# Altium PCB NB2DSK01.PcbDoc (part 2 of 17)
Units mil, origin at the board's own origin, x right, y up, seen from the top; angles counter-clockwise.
Board outline 11815 x 6500.03 mil, 8 copper layers (Top Layer, MidLayer1, MidLayer2, GND, PWR, MidLayer3, MidLayer4, Bottom Layer), stack 74.62 mil thick; 798 components, 1002 nets, 3927 pads, 3182 vias.
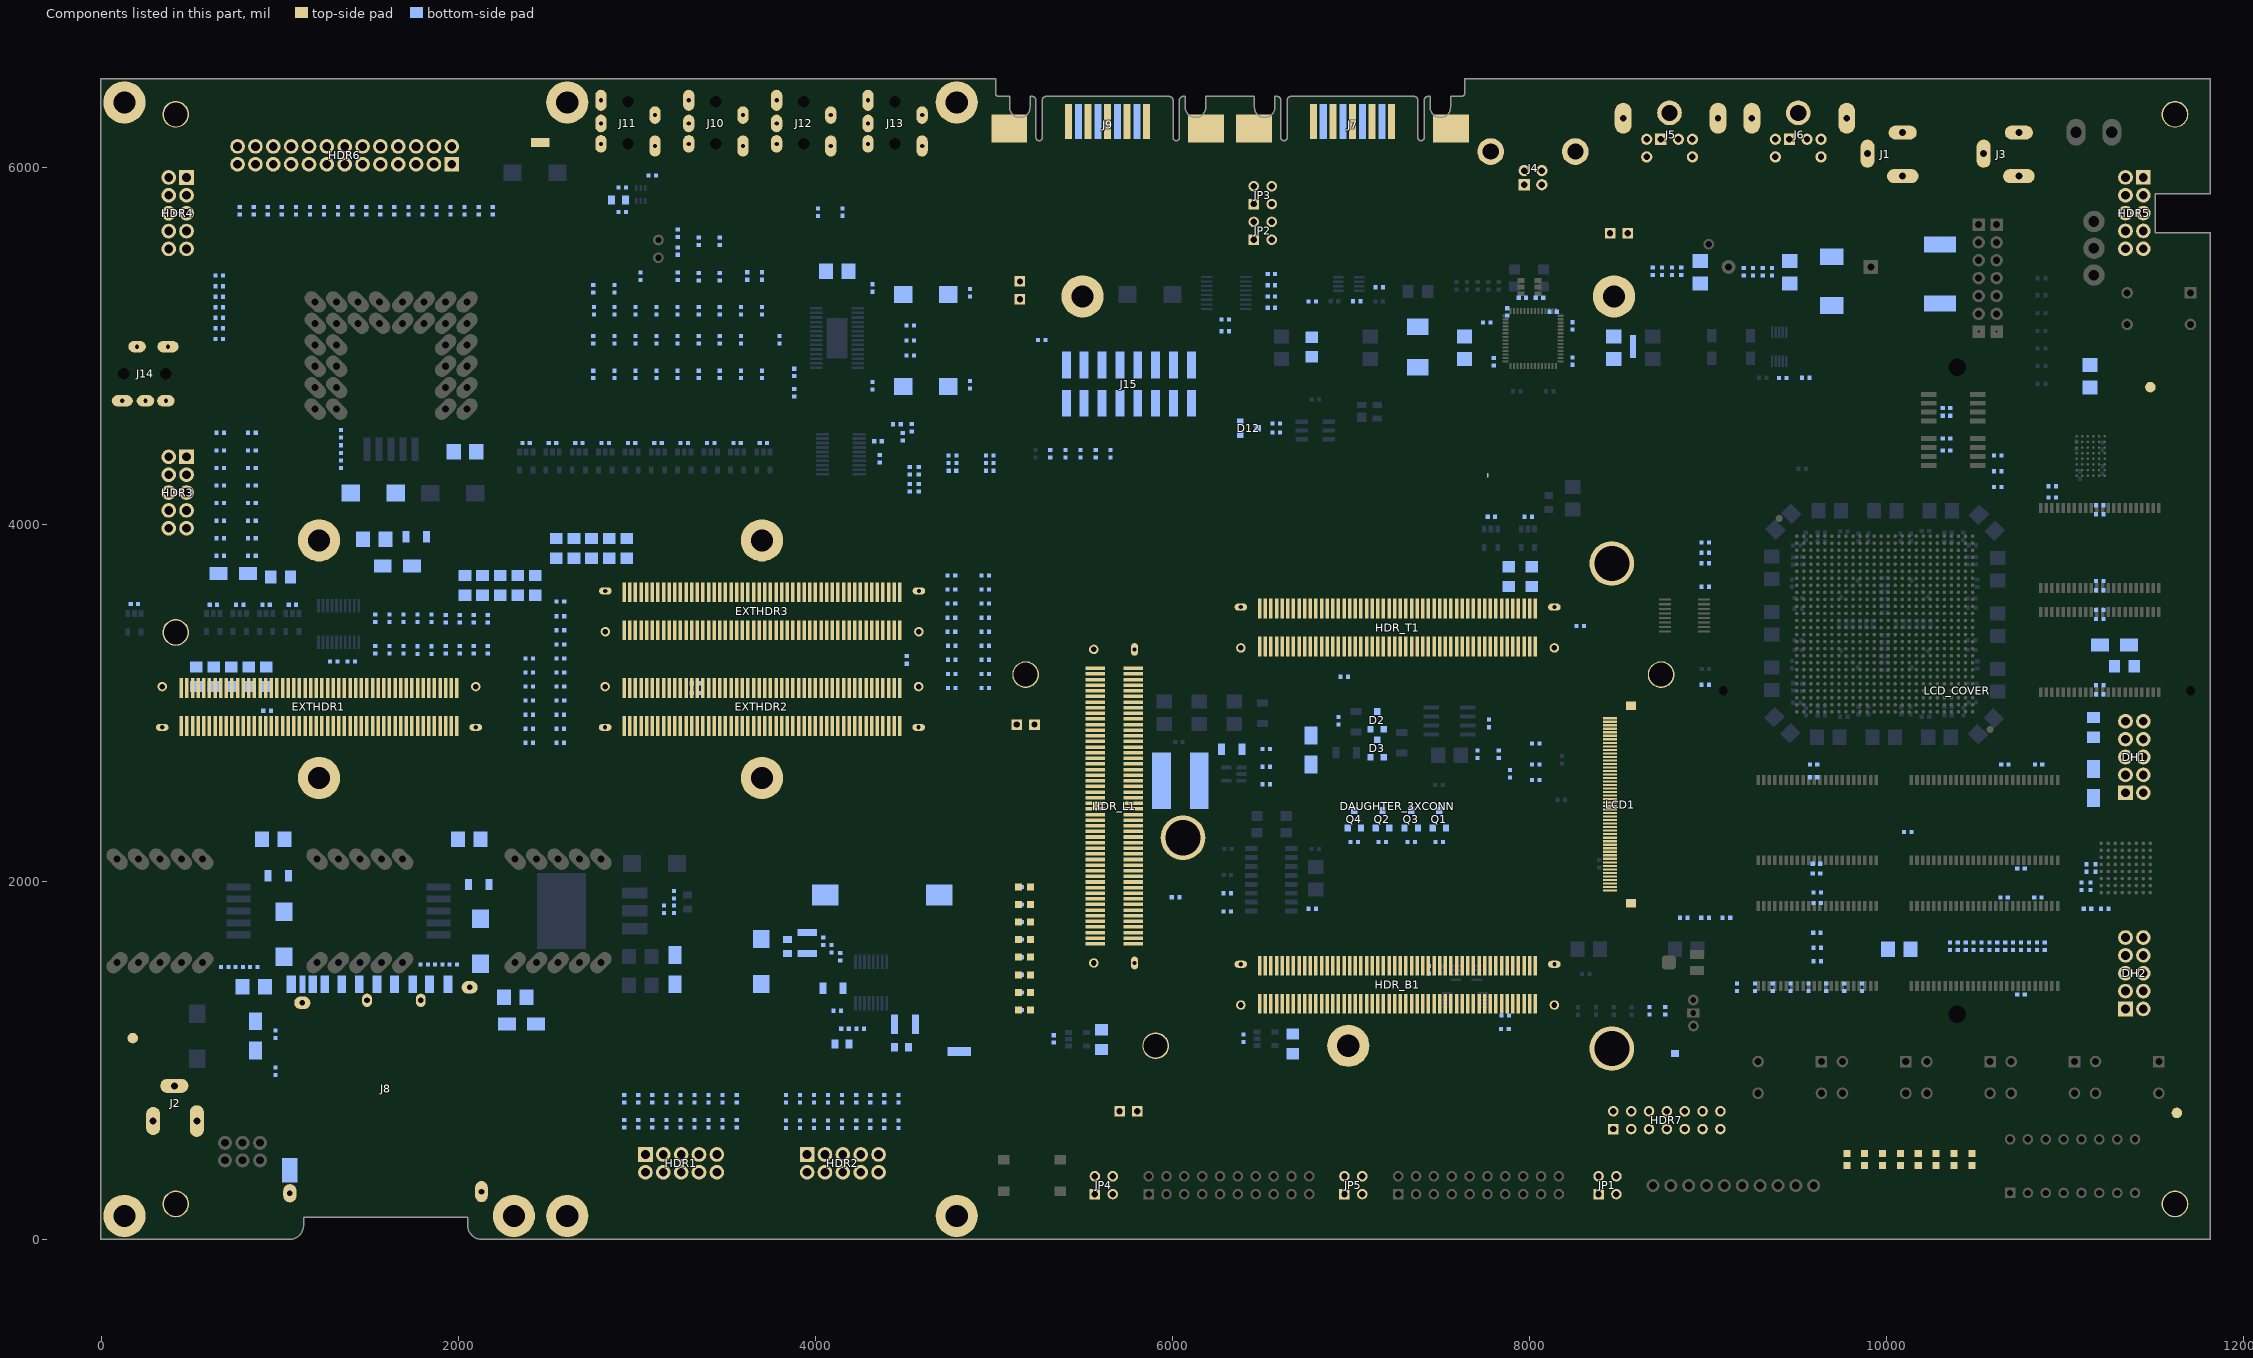
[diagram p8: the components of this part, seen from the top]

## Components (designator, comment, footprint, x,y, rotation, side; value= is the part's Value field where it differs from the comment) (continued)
C144 "1uF 25V" CAPC3216-STAR 6330.71,2744.1 r0 bottom locked (schematic designator C6)
C145 "470pF 50V" CAPC1005-STAR 4165.68,1178.45 r180 bottom (schematic designator C1)
C146 "10uF 10V" CAPC2012-STAR 4482.68,1074.45 r180 bottom (schematic designator C2)
C147 "22uF 10V" CAPC3225-STAR 4500.68,1203.45 r180 bottom (schematic designator C3)
C148 "10uF 10V" CAPC2012-STAR 3843.68,1638.45 r90 bottom (schematic designator C4)
C149 "22uF 10V" CAPC3225-STAR 3953.68,1658.45 r90 bottom (schematic designator C5)
C150 "220uF 10V" CAPC7343-STAR 3696.85,1555.12 r270 bottom (schematic designator C6)
C151 "1uF 25V" CAPC3216-STAR 4098.68,1405.45 r180 bottom (schematic designator C7)
C152 "10uF 10V" CAPC2012-STAR 4149.68,1093.45 r0 bottom (schematic designator C8)
C153 "0.1uF 16V" CAPC1005-STAR 6553.81,5405.51 r0 bottom (schematic designator C1)
C154 "0.1uF 16V" CAPC1005-STAR 6553.81,5342.52 r180 bottom (schematic designator C3)
C155 "0.1uF 16V" CAPC1005-STAR 6553.81,5279.53 r0 bottom (schematic designator C2)
C156 "0.1uF 16V" CAPC1005-STAR 6553.81,5216.54 r0 bottom (schematic designator C4)
C157 "1uF 25V" CAPC3216-STAR 2114.17,1986.59 r0 bottom (schematic designator C2)
C158 "10uF 20V" CAPC3528-STAR 2061.02,2238.45 r180 bottom (schematic designator C1)
C159 "10uF 20V" CAPC3528-STAR 2318.68,1353.45 r0 bottom (schematic designator C3)
C160 "220uF 10V" CAPC7343-STAR 2123.68,1668.45 r90 bottom (schematic designator C4)
C161 "1uF 25V" CAPC3216-STAR 992.13,2034.68 r0 bottom (schematic designator C2)
C162 "10uF 20V" CAPC3528-STAR 963.68,2238.45 r180 bottom (schematic designator C1)
C163 "10uF 20V" CAPC3528-STAR 853.68,1413.45 r180 bottom (schematic designator C3)
C164 "220uF 10V" CAPC7343-STAR 1023.68,1707.45 r90 bottom (schematic designator C4)
C165 "1uF 25V" CAPC3216-STAR 1763.68,3933.45 r180 bottom (schematic designator C2)
C166 "10uF 20V" CAPC3528-STAR 2037.4,4409.45 r0 bottom (schematic designator C1)
C167 "10uF 20V" CAPC3528-STAR 1528.68,3918.45 r0 bottom (schematic designator C3)
C168 "220uF 10V" CAPC7343-STAR 1523.68,4178.45 r0 bottom (schematic designator C4)
C169 "10uF 20V" CAPC3528-STAR 8955.24,5414.21 r270 bottom (schematic designator C1)
C170 "10uF 20V" CAPC3528-STAR 9456.18,5414.21 r270 bottom (schematic designator C1)
C171 "1uF 6.3v" CAPC1005-STAR 2874.02,4842.52 r270 bottom locked (schematic designator C6)
C172 "4.7nF 25V" CAPC1005-STAR 2755.91,4842.52 r270 bottom locked (schematic designator C7)
C173 "1uF 6.3v" CAPC1005-STAR 2992.13,4842.52 r270 bottom locked (schematic designator C8)
C174 "0.1uF 16V" CAPC1005-STAR 3881.89,4740.16 r270 bottom locked (schematic designator C15)
C175 "1uF 6.3v" CAPC1005-STAR 3346.46,4842.52 r270 bottom locked (schematic designator C9)
C176 "1uF 6.3v" CAPC1005-STAR 3582.68,4842.52 r270 bottom locked (schematic designator C11)
C177 "220uF 10V" CAPC7343-STAR 4618.11,5290.66 r0 bottom locked (schematic designator C12)
C178 "1uF 6.3v" CAPC1005-STAR 2755.91,5322.84 r90 bottom locked (schematic designator C26)
C179 "1uF 6.3v" CAPC1005-STAR 3228.68,5533.45 r270 bottom (schematic designator C13)
C180 "220uF 10V" CAPC7343-STAR 4618.11,4775.59 r0 bottom locked (schematic designator C16)
C181 "4.7nF 25V" CAPC1005-STAR 3228.68,5633.45 r90 bottom (schematic designator C50)
C182 "1uF 6.3v" CAPC1005-STAR 2874.02,5322.84 r90 bottom locked (schematic designator C27)
C183 "1uF 6.3v" CAPC1005-STAR 4531.49,4948.08 r0 bottom (schematic designator C10)
C184 "1uF 6.3v" CAPC1005-STAR 3110.24,4842.52 r270 bottom locked (schematic designator C17)
C185 "1uF 6.3v" CAPC1005-STAR 3228.35,4842.52 r270 bottom locked (schematic designator C19)
C186 "1uF 6.3v" CAPC1005-STAR 3700.79,4842.52 r270 bottom locked (schematic designator C20)
C187 "1uF 6.3v" CAPC1005-STAR 3346.46,5389.76 r270 bottom locked (schematic designator C18)
C188 "1uF 6.3v" CAPC1005-STAR 3618.11,5393.7 r90 bottom locked (schematic designator C21)
C189 "4.7nF 25V" CAPC1005-STAR 3700.79,5393.7 r270 bottom locked (schematic designator C22)
C190 "1uF 6.3v" CAPC1005-STAR 3464.57,5389.76 r270 bottom locked (schematic designator C14)
C191 "1uF 6.3v" CAPC1005-STAR 4151.97,5751.58 r270 bottom locked (schematic designator C4)
C192 "1uF 6.3v" CAPC1005-STAR 3464.57,4842.52 r270 bottom locked (schematic designator C5)
C193 "10uF 20V" CAPC3528-STAR 4122.05,5421.26 r180 bottom locked (schematic designator C23)
C194 "0.1uF 16V" CAPC1005-STAR 3881.89,4854.33 r90 bottom locked (schematic designator C24)
C195 "0.1uF 16V" CAPC1005-STAR 4318.9,4779.53 r270 bottom locked (schematic designator C25)
C196 "0.1uF 16V" CAPC1005-STAR 4318.9,5326.77 r270 bottom locked (schematic designator C28)
C197 "10uF 10V" CAPC2012-STAR 2897.64,5818.9 r0 bottom (schematic designator C1MIC)
C198 "0.1uF 16V" CAPC1005-STAR 3086.61,5956.68 r180 bottom (schematic designator C2MIC)
C199 "10nF 16V" CAPC1005-STAR 10334.65,4417.32 r180 bottom locked (schematic designator C1)
C200 "0.1uF 16V" CAPC1005-STAR 10334.63,4611.45 r0 bottom locked (schematic designator C2)
C201 "10nF 16V" CAPC1005-STAR 10334.65,4654.74 r180 bottom locked (schematic designator C3)
C202 "0.1uF 16V" CAPC1005-STAR 10334.65,4484.25 r0 bottom locked (schematic designator C4)
C203 "0.1uF 16V" CAPC1005-STAR 11192.91,4059.06 r180 bottom locked (schematic designator C1)
C204 "0.1uF 16V" CAPC1005-STAR 11192.91,3633.86 r0 bottom locked (schematic designator C2)
C205 "0.1uF 16V" CAPC1005-STAR 11192.91,3472.44 r180 bottom locked (schematic designator C3)
C206 "0.1uF 16V" CAPC1005-STAR 11192.91,3051.18 r0 bottom locked (schematic designator C4)
C207 "10nF 16V" CAPC1005-STAR 11192.91,4110.24 r180 bottom locked (schematic designator C5)
C208 "10nF 16V" CAPC1005-STAR 11192.91,3523.62 r180 bottom locked (schematic designator C6)
C209 "10nF 16V" CAPC1005-STAR 11192.91,3685.04 r0 bottom locked (schematic designator C7)
C210 "10nF 16V" CAPC1005-STAR 11192.91,3102.36 r0 bottom locked (schematic designator C8)
C211 "0.1uF 16V" CAPC1005-STAR 11118.11,2078.56 r270 bottom (schematic designator C1)
C212 "0.1uF 16V" CAPC1005-STAR 11090.55,1976.2 r270 bottom locked (schematic designator C2)
C213 "10nF 16V" CAPC1005-STAR 11220.51,1850.28 r0 bottom (schematic designator C3)
C214 "10nF 16V" CAPC1005-STAR 11169.29,2078.56 r270 bottom (schematic designator C4)
C215 "10nF 16V" CAPC1005-STAR 11141.73,1976.2 r270 bottom locked (schematic designator C5)
C216 "0.1uF 16V" CAPC1005-STAR 11124.11,1850.28 r180 bottom (schematic designator C6)
C217 "10uF 20V" CAPC3528-STAR 11138.28,4831.32 r270 bottom (schematic designator C23_CM)
C218 "10uF 20V" CAPC3528-STAR 10068.88,1623 r180 bottom (schematic designator C24_CM)
C219 "0.1uF 16V" CAPC1005-STAR 10661.42,2657.48 r180 bottom locked (schematic designator C1)
C220 "0.1uF 16V" CAPC1005-STAR 10751.97,2074.8 r180 bottom (schematic designator C2)
C221 "0.1uF 16V" CAPC1005-STAR 10657.48,1913.39 r180 bottom (schematic designator C3)
C222 "0.1uF 16V" CAPC1005-STAR 10751.97,1370.08 r180 bottom (schematic designator C4)
C223 "10nF 16V" CAPC1005-STAR 10850.39,2657.48 r180 bottom (schematic designator C5)
C224 "10nF 16V" CAPC1005-STAR 10117.22,2280.5 r180 bottom locked (schematic designator C6)
C225 "10nF 16V" CAPC1005-STAR 10846.46,1913.39 r180 bottom (schematic designator C7)
C226 "10nF 16V" CAPC1005-STAR 9608.95,1715.33 r0 bottom locked (schematic designator C8)
C227 "0.1uF 16V" CAPC1005-STAR 9606.3,2102.36 r0 bottom locked (schematic designator C1)
C228 "0.1uF 16V" CAPC1005-STAR 9590.55,2657.48 r180 bottom locked (schematic designator C2)
C229 "0.1uF 16V" CAPC1005-STAR 9610.24,1556.18 r0 bottom locked (schematic designator C3)
C230 "0.1uF 16V" CAPC1005-STAR 9610.24,1940.95 r180 bottom locked (schematic designator C4)
C231 "10nF 16V" CAPC1005-STAR 9606.3,2047.24 r0 bottom locked (schematic designator C5)
C232 "10nF 16V" CAPC1005-STAR 9590.55,2586.61 r180 bottom locked (schematic designator C6)
C233 "10nF 16V" CAPC1005-STAR 9610.24,1631.93 r0 bottom (schematic designator C7)
C234 "10nF 16V" CAPC1005-STAR 9610.24,1881.89 r180 bottom locked (schematic designator C8)
C235 "0.1uF 16V" CAPC1005-STAR 7785.43,4045.28 r180 bottom (schematic designator C6CS)
C236 "0.1uF 16V" CAPC1005-STAR 1070.96,3553.15 r180 bottom (schematic designator C11CS)
C237 "0.1uF 16V" CAPC1005-STAR 3708.76,4458.66 r180 bottom (schematic designator C1CS)
C238 "0.1uF 16V" CAPC1005-STAR 3265.85,4458.66 r180 bottom (schematic designator C7CS)
C239 "0.1uF 16V" CAPC1005-STAR 3561.12,4458.66 r180 bottom (schematic designator C12CS)
C240 "0.1uF 16V" CAPC1005-STAR 7992.13,4045.28 r180 bottom (schematic designator C2CS)
C241 "0.1uF 16V" CAPC1005-STAR 2970.57,4458.66 r180 bottom (schematic designator C13CS)
C242 "0.1uF 16V" CAPC1005-STAR 775.69,3553.15 r180 bottom (schematic designator C3CS)
C243 "0.1uF 16V" CAPC1005-STAR 2822.93,4458.66 r180 bottom (schematic designator C8CS)
C244 "0.1uF 16V" CAPC1005-STAR 923.33,3553.15 r180 bottom (schematic designator C9CS)
C245 "0.1uF 16V" CAPC1005-STAR 628.05,3553.15 r180 bottom (schematic designator C14CS)
C246 "0.1uF 16V" CAPC1005-STAR 186.22,3556.84 r180 bottom (schematic designator C4CS)
C247 "0.1uF 16V" CAPC1005-STAR 3413.48,4458.66 r180 bottom (schematic designator C10CS)
C248 "0.1uF 16V" CAPC1005-STAR 2675.3,4458.66 r180 bottom (schematic designator C5CS)
C249 "0.1uF 16V" CAPC1005-STAR 3118.21,4458.66 r180 bottom (schematic designator C15CS)
C250 "0.1uF 16V" CAPC1005-STAR 2527.66,4458.66 r180 bottom (schematic designator C16CS)
C251 "0.1uF 16V" CAPC1005-STAR 5334.73,1121.45 r270 bottom (schematic designator C18CS)
C252 "0.1uF 16V" CAPC1005-STAR 2380.02,4458.66 r180 bottom (schematic designator C17CS)
C253 "0.1uF 16V" CAPC1005-STAR 6398.2,1124.47 r270 bottom (schematic designator C19CS)
C254 "0.1uF 16V" CAPC1005-STAR 4360.24,4370.08 r270 bottom (schematic designator C1_CS)
C255 "0.1uF 16V" CAPC1005-STAR 1302.09,3234.1 r180 bottom (schematic designator C2_CS)
C256 "0.1uF 16V" CAPC1005-STAR 1400.51,3234.09 r180 bottom (schematic designator C26_CS)
C257 "0.1uF 16V" CAPC1005-STAR 4350.39,4468.5 r0 bottom (schematic designator C25_CS)
C258 "0.1uF 16V" CAPC1005-STAR 4976.38,4303.15 r0 bottom (schematic designator C20CS)
C259 "0.1uF 16V" CAPC1005-STAR 4767.72,4303.15 r180 bottom (schematic designator C21CS)
C260 "0.1uF 16V" CAPC1005-STAR 4538.92,4543.61 r270 bottom (schematic designator C22CS)
C261 "0.1uF 16V" CAPC1005-STAR 4528.77,4303.15 r270 bottom (schematic designator C23CS)
C262 "0.1uF 16V" CAPC1005-STAR 4578.74,4303.15 r270 bottom (schematic designator C24CS)
C263 "0.1uF 16V" CAPC1005-STAR 7874,5192.9 r270 bottom (schematic designator C4_US)
C264 "0.1uF 16V" CAPC1005-STAR 8240.16,4917.32 r270 bottom locked (schematic designator C6_US)
C265 "0.1uF 16V" CAPC1005-STAR 8240.16,5114.17 r90 bottom (schematic designator C7_US)
C266 "10uF 20V" CAPC3528-STAR 7635.07,4992.74 r270 bottom locked (schematic designator C3_US)
C267 "0.1uF 16V" CAPC1005-STAR 7759.84,5133.86 r180 bottom locked (schematic designator C5_US)
C268 "0.1uF 16V" CAPC1005-STAR 7799.21,4913.39 r270 bottom locked (schematic designator C8_US)
C269 "22pF 50V" CAPC1005-STAR 8055.12,5272.46 r180 bottom (schematic designator C1_US)
C270 "22pF 50V" CAPC1005-STAR 7959.61,5272.46 r0 bottom (schematic designator C2_US)
C271 "4.7nF 250V" CAPM7163 7373.44,4996.05 r270 bottom locked (schematic designator C11_US)
C272 "0.1uF 16V" CAPC1005-STAR 8131.35,5193.1 r180 bottom (schematic designator C10_US)
C273 "10uF 20V" CAPC3528-STAR 8470.68,4991.08 r270 bottom (schematic designator C9_US)
D1 "5V 5W" DIOM8059 9691.93,5364.54 r90 bottom locked
D2 "35mA 7.5V" SOT95P230-3D 7145.67,2905.51 r180 bottom locked (schematic designator D1)
D3 "200mA 30V" SOT95P230-3C 7145.67,2748.03 r180 bottom locked (schematic designator D2)
D4 "3A 40V" DIOM5027 3213.72,1508.86 r90 bottom locked (schematic designator D1)
D5 "3A 40V" DIOM5027 6775.59,2739.17 r90 bottom (schematic designator D1)
D6 "3A 40V" DIOM5027 2353.68,1203.45 r0 bottom (schematic designator D1)
D7 "3A 40V" DIOM5027 863.68,1138.45 r270 bottom (schematic designator D1)
D8 "3A 40V" DIOM5027 1658.68,3768.45 r0 bottom (schematic designator D1)
D9 "3A 40V" DIOM5027 11275.57,3326.76 r180 bottom (schematic designator D10)
D10 "3A 40V" DIOM5027 11157.46,2551.18 r270 bottom
D11 "3A 40V" DIOM5027 739.47,3727.35 r180 bottom (schematic designator D12)
D12 "3.3V" SOT95P230-3D 6427.82,4542 r90 bottom (schematic designator D1)
DAUGHTER_3XCONN "Comment" DAUGHTER_BOARD_3XCONN 6984.25,1082.68 r0 top locked
DH1 "2x5 R/A HEADER BOXED MALE" 918510X323#1 11437.01,2700 r90 bottom locked
DH2 "2x5 R/A HEADER BOXED MALE" 918510X323#1 11437.01,1488.98 r90 bottom locked (schematic designator DH1)
EXTHDR1 "NANOCONNECT" 53751 1220.47,2980.32 r180 top locked (schematic designator EXTHDR)
EXTHDR2 "NANOCONNECT" 53751 3700.79,2980.32 r180 top locked (schematic designator EXTHDR)
EXTHDR3 "NANOCONNECT" 53751 3700.79,3515.75 r0 top locked (schematic designator EXTHDR)
F1 "MF-SM300-2" MF_SM250 10303.13,5478.17 r270 bottom
F2 "MF-NSMF035 350mA" RESC3216 6779.51,4996.05 r90 bottom (schematic designator F6)
F3 "MF-NSMF035 350mA" RESC3216 11330.71,3208.66 r180 bottom (schematic designator F4)
F4 "MF-NSMF035 350mA" RESC3216 11157.46,2866.14 r90 bottom
F5 "MF-NSMF035 350mA" RESC3216 1005.16,3708.28 r0 bottom (schematic designator F1)
FD1 "Fiducial - Round" "FIDUCIAL ROUND" 11476.36,4771.64 r90 top (schematic designator FD3)
FD2 "Fiducial - Round" "FIDUCIAL ROUND" 11624.68,706.45 r90 top (schematic designator FD1)
FD3 "Fiducial - Round" "FIDUCIAL ROUND" 177.17,1125.98 r90 top (schematic designator FD2)
FP1 "Daughterboard Mounting Holes" DAUGHTER_BOARD_2XCONN 7259.84,2425.2 r0 top locked
GP1 "1x2 HEADER Male" HDR1X2 5226.46,2881.88 r180 top locked
GP2 "1x2 HEADER Male" HDR1X2 8450.68,5632.45 r0 top
GP3 "1x2 HEADER Male" HDR1X2 5145.66,5263.77 r90 top locked
GP4 "1x2 HEADER Male" HDR1X2 5703.53,716.24 r0 top locked
HDR1 "2x5 R/A HEADER BOXED MALE" 918510X323#1 3248.03,374.02 r0 bottom locked
HDR2 "2x5 R/A HEADER BOXED MALE" 918510X323#1 4153.54,374.02 r0 bottom locked (schematic designator HDR1)
HDR3 "2x5 R/A HEADER BOXED MALE" 918510X323#1 377.95,4181.1 r270 bottom locked (schematic designator HDR1)
HDR4 "2x5 RA HEADER MALE" 918510X323#2 377.95,5745.67 r90 bottom (schematic designator HDR1)
HDR5 "2x5 RA HEADER" 918510X323#3 11437.01,5746.06 r90 bottom locked (schematic designator HDR2)
HDR6 "2x13 R/A HEADER BOXED MALE" HDR2X13_RA_CENTRONICS 1363.78,6119.69 r180 bottom locked (schematic designator HDR1)
HDR7 "2x7 HEADER MALE" HDR2X7 8468.5,616.54 r0 top locked (schematic designator HDR1)
HDR_B1 "NANOCONNECT" 53751 7259.84,1425.2 r0 top locked (schematic designator HDR_B)
HDR_L1 "NANOCONNECT" 53751 5673.23,2425.2 r270 top locked (schematic designator HDR_L)
HDR_T1 "NANOCONNECT" 53751 7259.84,3425.2 r0 top locked (schematic designator HDR_T)
J1 "POWERJACK 3 HEADER" KLD-0202 10089.37,6492.13 r270 top locked (schematic designator J11)
J2 "POWERJACK 3 HEADER" KLD-0202 -3.94,661.42 r0 bottom (schematic designator J1OUT)
J3 "POWERJACK 3 HEADER" KLD-0202 10739.76,6492.13 r270 top locked (schematic designator J12)
J4 "USB B HEADER" 440119 8018.9,5944.49 r90 top locked (schematic designator J1)
J5 "MINIDIN 6P PURPLE" MINIDIN6PURPLE 8783.46,6492.13 r270 top locked (schematic designator J1)
J6 "MINIDIN 6P GREEN" MINIDIN6GREEN 9503.94,6492.13 r270 top locked (schematic designator J1)
J7 "070221XE009GX14BU" 070221XE009GX14BU#1 7008,6259.84 r0 top locked (schematic designator J1)
J8 "SD CARD HEADER" SD_CARD_HRS_609_0003_5 1568.68,1378.45 r180 bottom locked (schematic designator J1)
J9 "070221XE009GX14BU" 070221XE009GX14BU#2 5636.78,6259.84 r0 top locked (schematic designator J1)
J10 "AUDIO BLACK HEADER" TSH-3675 3442.28,6370.08 r270 bottom locked (schematic designator J1)
J11 "AUDIO PINK HEADER" TSH-3675 2950.16,6370.08 r270 bottom locked (schematic designator J2)
J12 "AUDIO GREEN HEADER" TSH-3675 3934.41,6370.08 r270 bottom locked (schematic designator J3)
J13 "AUDIO BLUE HEADER" TSH-3675 4446.22,6370.08 r270 bottom locked (schematic designator J4)
J14 "AUDIO BLACK HEADER" TSH-3675 125.98,4846.46 r0 bottom locked (schematic designator J5)
J15 "TYCO 969973-8" HDR2X8_SMT 6105.23,4681.09 r180 bottom locked (schematic designator J1)
JP1 "2x2 HEADER MALE" HDR2X2 8385.83,251.97 r0 top locked
JP2 "2x2 HEADER MALE" HDR2X2 6455.12,5596.85 r0 top locked
JP3 "2x2 HEADER MALE" HDR2X2 6455.12,5796.85 r0 top locked (schematic designator JP1)
JP4 "2x2 HEADER MALE" HDR2X2 5565.12,251.81 r0 top locked (schematic designator JP1)
JP5 "2x2 HEADER MALE" HDR2X2 6962.76,251.81 r0 top locked (schematic designator JP2)
L1 "10uH 2.3A 70mR" INDP7575 6043.31,2566.93 r0 bottom locked
L2 "2.2uH 9A 6.8mR" INDP182140 4374.68,1927.45 r180 bottom locked (schematic designator L1)
LCD1 "LCD HEADER" HITACHI_TX09D50VM1CAA 9086.61,3070.87 r0 top locked
LCD_COVER "Comment" LCD_COVER 10393.7,4881.89 r0 top locked
LED1 "0603 LED" 0603LED 5171.26,1972.44 r180 top locked (schematic designator LED0)
LED2 "0603 LED" 0603LED 5171.26,1874.02 r180 top locked (schematic designator LED1)
LED3 "0603 LED" 0603LED 5171.26,1775.59 r180 top locked (schematic designator LED2)
LED4 "0603 LED" 0603LED 5171.26,1677.17 r180 top locked (schematic designator LED3)
LED5 "0603 LED" 0603LED 5171.26,1578.74 r180 top locked (schematic designator LED4)
LED6 "0603 LED" 0603LED 5171.26,1480.32 r180 top locked (schematic designator LED5)
LED7 "0603 LED" 0603LED 5171.26,1381.89 r180 top locked (schematic designator LED6)
LED8 "0603 LED" 0603LED 5171.26,1283.47 r180 top locked (schematic designator LED7)
LED9 "LED, Green, 0603 (1608)" 0603LED 10476.38,445.94 r270 top locked (schematic designator LED0)
LED10 "LED, Green, 0603 (1608)" 0603LED 10376.38,445.95 r270 top locked (schematic designator LED1)
LED11 "LED, Green, 0603 (1608)" 0603LED 10276.38,445.95 r270 top locked (schematic designator LED2)
LED12 "LED, Green, 0603 (1608)" 0603LED 10176.38,445.95 r270 top locked (schematic designator LED3)
LED13 "LED, Green, 0603 (1608)" 0603LED 10076.38,445.95 r270 top locked (schematic designator LED4)
LED14 "LED, Green, 0603 (1608)" 0603LED 9976.38,445.95 r270 top locked (schematic designator LED5)
LED15 "LED, Green, 0603 (1608)" 0603LED 9876.38,445.95 r270 top locked (schematic designator LED6)
LED16 "LED, Green, 0603 (1608)" 0603LED 9776.38,445.95 r270 top locked (schematic designator LED7)
LOGO1 "Nanoboard Logo" "NANOBOARD LOGO" 6753.7,650.76 r180 bottom
LOGO2 "Nanoboard Logo" "NANOBOARD LOGO" 6960.63,744.09 r0 top
MH1 "MOUNTING HOLE 3MM" MOUNTING_HOLE_3MM 11614.17,196.85 r180 top locked
MH2 "MOUNTING HOLE 3MM" MOUNTING_HOLE_3MM 417.32,3397.64 r180 top locked (schematic designator MH6)
MH3 "MOUNTING HOLE 3MM" MOUNTING_HOLE_3MM 417.32,196.85 r0 top locked (schematic designator MH2)
MH4 "MOUNTING HOLE 3MM" MOUNTING_HOLE_3MM 5177.17,3161.42 r0 top locked (schematic designator MH7)
MH5 "MOUNTING HOLE 3MM" MOUNTING_HOLE_3MM 417.32,6299.21 r90 top locked (schematic designator MH3)
MH6 "MOUNTING HOLE 3MM" MOUNTING_HOLE_3MM 5905.51,1082.68 r180 top locked (schematic designator MH8)
MH7 "MOUNTING HOLE 3MM" MOUNTING_HOLE_3MM 11614.17,6299.21 r0 top locked (schematic designator MH4)
MH8 "MOUNTING HOLE 3MM" MOUNTING_HOLE_3MM 8736.22,3161.42 r180 top locked (schematic designator MH5)
NT1 "Net Tie SMT2" NETTIE-SMT2-31X51#1 4814.68,1051.45 r0 bottom net-tie (schematic designator NT2)
NT2 "Net Tie SMT2" NETTIE-SMT2-16X11 8784.2,1066.5 r180 bottom net-tie (schematic designator NT1)
NT3 "Net Tie SMT2" NETTIE-SMT2-8X8#1 10452.68,1525.45 r270 top net-tie (schematic designator NT8)
NT4 "Net Tie SMT2" NETTIE-SMT2-31X39 2411.9,6142.8 r180 top net-tie (schematic designator NT1)
NT5 "Net Tie SMT2" NETTIE-SMT2-31X51#2 8578.72,5007.86 r90 bottom net-tie (schematic designator NT3)
NT6 "Net Tie SMT2" NETTIE-SMT2-8X8#2 7764.76,4247.05 r270 bottom net-tie (schematic designator NT1_CS)
PB_MH1 "MOUNTING HOLE 3MM SOLDER STANDOFF" STANDOFF_SOLDER_3MM 129.92,6366.14 r90 top locked (schematic designator PB_MH7)
PB_MH2 "MOUNTING HOLE 3MM SOLDER STANDOFF" STANDOFF_SOLDER_3MM 1220.47,2582.68 r180 top locked (schematic designator PB_MH1)
PB_MH3 "MOUNTING HOLE 3MM SOLDER STANDOFF" STANDOFF_SOLDER_3MM 2610.24,6366.14 r180 top locked (schematic designator PB_MH8)
PB_MH4 "MOUNTING HOLE 3MM SOLDER STANDOFF" STANDOFF_SOLDER_3MM 129.92,129.92 r180 top locked (schematic designator PB_MH2)
PB_MH5 "MOUNTING HOLE 3MM SOLDER STANDOFF" STANDOFF_SOLDER_3MM 4791.34,6366.14 r270 top locked (schematic designator PB_MH9)
PB_MH6 "MOUNTING HOLE 3MM SOLDER STANDOFF" STANDOFF_SOLDER_3MM 2311.02,129.92 r270 top locked (schematic designator PB_MH3)
PB_MH7 "MOUNTING HOLE 3MM SOLDER STANDOFF" STANDOFF_SOLDER_3MM 3700.79,3913.39 r180 top locked (schematic designator PB_MH10)
PB_MH8 "MOUNTING HOLE 3MM SOLDER STANDOFF" STANDOFF_SOLDER_3MM 1220.47,3913.39 r180 top locked (schematic designator PB_MH11)
PB_MH9 "MOUNTING HOLE 3MM SOLDER STANDOFF" STANDOFF_SOLDER_3MM 3700.79,2582.68 r180 top locked (schematic designator PB_MH4)
PB_MH10 "MOUNTING HOLE 3MM SOLDER STANDOFF" STANDOFF_SOLDER_3MM 5496.06,5279.53 r90 top locked (schematic designator PB_MH12)
PB_MH11 "MOUNTING HOLE 3MM SOLDER STANDOFF" STANDOFF_SOLDER_3MM 2610.24,129.92 r180 top locked (schematic designator PB_MH5)
PB_MH12 "MOUNTING HOLE 3MM SOLDER STANDOFF" STANDOFF_SOLDER_3MM 8472.44,5279.53 r90 top locked (schematic designator PB_MH13)
PB_MH13 "MOUNTING HOLE 3MM SOLDER STANDOFF" STANDOFF_SOLDER_3MM 4791.34,129.92 r270 top locked (schematic designator PB_MH6)
PB_MH14 "MOUNTING HOLE 3MM SOLDER STANDOFF" STANDOFF_SOLDER_3MM 6984.25,1082.68 r90 top locked
PBFREE "" LEAD_FREE_S 4614.17,4990 r0 top
PBOARD_A "Comment" PERIPHERAL_BOARD_1SLOT#1 2440.96,3228.34 r180 top locked
PBOARD_B "Comment" PERIPHERAL_BOARD_1SLOT#2 4921.26,3228.35 r180 top locked
PBOARD_C "Comment" PERIPHERAL_BOARD_2SLOT 0,3267.72 r0 top locked
Q1 "TRA-NPN-40V-40V-5V-SOT23" SOT95P230-3C 7494.42,2351.65 r180 bottom locked
Q2 "TRA-NPN-40V-40V-5V-SOT23" SOT95P230-3C 7175.52,2351.65 r180 bottom locked
Q3 "TRA-NPN-40V-40V-5V-SOT23" SOT95P230-3C 7336.93,2351.65 r180 bottom locked
Q4 "TRA-NPN-40V-40V-5V-SOT23" SOT95P230-3C 7018.04,2351.65 r180 bottom locked
R1 "4k7 1%" RESC1005-STAR 9417.94,4823 r0 bottom locked
R2 "27R 1%" RESC1005-STAR 9546.82,4823.89 r180 bottom locked
R3 "5R6 1%" RESC1005-STAR 6307.09,1937.01 r0 bottom locked (schematic designator R1)
R4 "5R6 1%" RESC1005-STAR 6783.47,1850.39 r180 bottom locked (schematic designator R2)
R5 "1K 1%" RESC1005-STAR 6307.09,1834.65 r180 bottom locked (schematic designator R3)
R6 "4K7 1%" RESC1005-STAR 8670.97,1278.04 r90 bottom (schematic designator R1)
R7 "4K7 1%" RESC1005-STAR 8759.97,1278.04 r90 bottom (schematic designator R2)
R8 "100R 1%" RESC1005-STAR 7863.79,1251.8 r0 bottom (schematic designator R3)
R9 "100R 1%" RESC1005-STAR 7861.82,1177 r0 bottom (schematic designator R4)
R10 "5R6 1%" RESC1005-STAR 7436.99,1507.87 r270 bottom (schematic designator R5)
R11 "4K7 1%" RESC1005-STAR 8983.28,3784.68 r180 bottom (schematic designator R1)
R12 "4K7 1%" RESC1005-STAR 10927.17,4216.54 r180 bottom locked (schematic designator R7_S3)
R13 "4K7 1%" RESC1005-STAR 10620.46,4300.43 r0 bottom (schematic designator R4)
R14 "4K7 1%" RESC1005-STAR 10620.46,4212.6 r0 bottom (schematic designator R5_S3)
R15 "100R 1%" RESC1005-STAR 8983.28,3902.07 r0 bottom (schematic designator R24)
R16 "100R 1%" RESC1005-STAR 10927.17,4153.35 r180 bottom (schematic designator R15)
R17 "5R6 1%" RESC1005-STAR 8983.28,3653.54 r0 bottom (schematic designator R1_HOST)
R18 "2K2 1%" RESC1005-STAR 8283.68,3433.45 r180 bottom (schematic designator R2)
R19 "4K7 1%" RESC1005-STAR 6960.62,3149.6 r180 bottom (schematic designator R1)
R20 "2K2 1%" RESC1005-STAR 3328.68,3058.45 r0 bottom (schematic designator R3)
R21 "47R 1%" RESC1005-STAR 775.59,5759.84 r270 bottom locked (schematic designator R8_PP)
R22 "47R 1%" RESC1005-STAR 854.33,5759.84 r270 bottom locked (schematic designator R10_PP)
R23 "47R 1%" RESC1005-STAR 933.07,5759.84 r270 bottom locked (schematic designator R11_PP)
R24 "47R 1%" RESC1005-STAR 1011.81,5759.84 r270 bottom locked (schematic designator R12_PP)
R25 "100R 1%" RESC1005-STAR 1090.55,5759.84 r90 bottom locked (schematic designator R13_PP)
R26 "100R 1%" RESC1005-STAR 1169.29,5759.84 r90 bottom locked (schematic designator R14_PP)
R27 "100R 1%" RESC1005-STAR 1248.03,5759.84 r90 bottom locked (schematic designator R16_PP)
R28 "100R 1%" RESC1005-STAR 1326.77,5759.84 r90 bottom locked (schematic designator R17_PP)
R29 "100R 1%" RESC1005-STAR 1405.51,5759.84 r90 bottom locked (schematic designator R18_PP)
R30 "100R 1%" RESC1005-STAR 1641.73,5759.84 r90 bottom locked (schematic designator R19_PP)
R31 "100R 1%" RESC1005-STAR 1799.21,5759.84 r90 bottom locked (schematic designator R20_PP)
R32 "100R 1%" RESC1005-STAR 2035.43,5759.84 r90 bottom locked (schematic designator R21_PP)
R33 "100R 1%" RESC1005-STAR 2192.91,5759.84 r90 bottom locked (schematic designator R22_PP)
R34 "1K 1%" RESC1005-STAR 1484.25,5759.84 r270 bottom locked (schematic designator R1)
R35 "100R 1%" RESC1005-STAR 2114.17,5759.84 r90 bottom locked (schematic designator R23_PP)
R36 "47R 1%" RESC1005-STAR 1956.69,5759.84 r270 bottom locked (schematic designator R24_PP)
R37 "100R 1%" RESC1005-STAR 1877.95,5759.84 r90 bottom locked (schematic designator R25_PP)
R38 "100R 1%" RESC1005-STAR 1720.47,5759.84 r90 bottom locked (schematic designator R26_PP)
R39 "1K 1%" RESC1005-STAR 1562.99,5759.84 r90 bottom locked (schematic designator R27_PP)
R40 "47K 1%" RESC1005-STAR 9102.34,1799.21 r180 bottom (schematic designator R2)
R41 "3K9 1%" RESC1005-STAR 8862.19,1799.21 r180 bottom (schematic designator R1)
R42 "47K 1%" RESC1005-STAR 8982.27,1799.21 r180 bottom (schematic designator R3)
R43 "1K 1%" RESC1005-STAR 7889.76,2606.3 r90 bottom locked (schematic designator R9)
R44 "5K6 1%" RESC1005-STAR 8033.46,2775.59 r0 bottom locked (schematic designator R10)
R45 "15K 1%" RESC1005-STAR 8033.46,2657.48 r0 bottom locked (schematic designator R12)
R46 "15K 1%" RESC1005-STAR 8033.46,2570.87 r0 bottom locked (schematic designator R11)
R47 "47K 1%" RESC1005-STAR 8984.22,3104.85 r0 bottom locked (schematic designator R19)
R48 "1K 1%" RESC1005-STAR 7494.41,2223.69 r0 bottom (schematic designator R4)
R49 "1K 1%" RESC1005-STAR 7175.52,2223.69 r0 bottom locked (schematic designator R5)
R50 "27R 1%" RESC1005-STAR 7336.93,2223.69 r0 bottom locked (schematic designator R6)
R51 "27R 1%" RESC1005-STAR 7018.04,2223.69 r0 bottom locked (schematic designator R7)
R52 "4K7 1%" RESC1005-STAR 10620.46,4388.25 r0 bottom (schematic designator R1)
R53 "270R 1%" RESC1005-STAR 7031.97,5251.96 r0 bottom (schematic designator R1)
R54 "120R 1%" RESC1005-STAR 6782.39,5251.05 r0 bottom (schematic designator R2)
R55 "15K 1%" RESC1005-STAR 7157.47,5330.7 r0 bottom (schematic designator R3)
R56 "4K7 1%" RESC1005-STAR 6929.13,2903.54 r90 bottom locked (schematic designator R1)
R57 "220R 1%" RESC1005-STAR 7771.65,2887.8 r90 bottom locked (schematic designator R1)
R58 "2K7 1%" RESC1005-STAR 7708.54,2714.57 r90 bottom (schematic designator R2)
R59 "2K7 1%" RESC1005-STAR 7826.65,2714.57 r90 bottom (schematic designator R3)
R60 "120R 1%" RESC1005-STAR 3151.97,1846.85 r90 bottom locked (schematic designator R1)
R61 "47R 1%" RESC1005-STAR 3208.68,1847.82 r90 bottom (schematic designator R2)
R62 "5R6 1%" RESC1005-STAR 3208.66,1929.63 r90 bottom (schematic designator R3)
R63 "100K 1%" RESC1005-STAR 6525.59,2744.1 r0 bottom locked (schematic designator R1)
R64 "8K2 1%" RESC1005-STAR 6525.59,2547.24 r180 bottom locked (schematic designator R2)
R65 "680K 1%" RESC1005-STAR 6525.59,2645.67 r180 bottom locked (schematic designator R3)
R66 "33R 1%" RESC1005-STAR 4250.68,1178.45 r0 bottom (schematic designator R1)
R67 "2K7 1%" RESC1005-STAR 4043.68,1668.45 r90 bottom (schematic designator R2)
R68 "27K 1%" RESC1005-STAR 4090.68,1626.45 r90 bottom (schematic designator R3)
R69 "100K 1%" RESC1005-STAR 4121.68,1278.45 r0 bottom (schematic designator R4)
R70 "2K7 1%" RESC1005-STAR 4138.68,1581.45 r90 bottom (schematic designator R5)
R71 "100R 1%" RESC1005-STAR 6294.35,5084 r180 bottom locked (schematic designator R1)
R72 "100R 1%" RESC1005-STAR 6294.35,5150.61 r180 bottom locked (schematic designator R2)
R73 "10K 1%" RESC1005-STAR 1972.72,1538.45 r180 bottom (schematic designator R1)
R74 "330R 1%" RESC1005-STAR 1890.83,1538.45 r180 bottom (schematic designator R2)
R75 "22K 1%" RESC1005-STAR 1808.68,1538.45 r0 bottom (schematic designator R3)
R76 "22K 1%" RESC1005-STAR 853.66,1523.45 r0 bottom (schematic designator R1)
R77 "1K 1%" RESC1005-STAR 773.68,1523.45 r180 bottom (schematic designator R2)
R78 "22K 1%" RESC1005-STAR 692.1,1523.45 r180 bottom (schematic designator R3)
R79 "22K 1%" RESC1005-STAR 1343.68,4339.85 r270 bottom (schematic designator R1)
R80 "3K3 1%" RESC1005-STAR 1343.68,4424.85 r270 bottom (schematic designator R2)
R81 "15K 1%" RESC1005-STAR 1343.68,4509.85 r270 bottom (schematic designator R3)
R82 "4K7 1%" RESC1005-STAR 976.38,1147.64 r90 bottom locked (schematic designator R1)
R83 "4K7 1%" RESC1005-STAR 976.38,940.95 r270 bottom locked (schematic designator R2)
R84 "4K7 1%" RESC1005-STAR 8689.73,5420.51 r90 bottom locked (schematic designator R1)
R85 "4K7 1%" RESC1005-STAR 8848.51,5420.51 r90 bottom locked (schematic designator R2)
R86 "100R 1%" RESC1005-STAR 8796.9,5420.51 r90 bottom locked (schematic designator R3)
R87 "100R 1%" RESC1005-STAR 8741.35,5420.51 r90 bottom locked (schematic designator R4)
R88 "4K7 1%" RESC1005-STAR 9198.54,5416.58 r90 bottom (schematic designator R1)
R89 "4K7 1%" RESC1005-STAR 9357.32,5416.58 r90 bottom (schematic designator R2)
R90 "100R 1%" RESC1005-STAR 9305.71,5416.58 r90 bottom (schematic designator R3)
R91 "100R 1%" RESC1005-STAR 9250.16,5416.58 r90 bottom (schematic designator R4)
R92 "270R 1%" RESC1005-STAR 5178.35,1972.44 r0 bottom locked (schematic designator R1)
R93 "270R 1%" RESC1005-STAR 5178.35,1874.02 r0 bottom locked (schematic designator R2)
R94 "270R 1%" RESC1005-STAR 5178.35,1775.59 r0 bottom locked (schematic designator R3)
R95 "270R 1%" RESC1005-STAR 5178.35,1677.17 r0 bottom locked (schematic designator R4)
R96 "270R 1%" RESC1005-STAR 5178.35,1578.74 r0 bottom locked (schematic designator R5)
R97 "270R 1%" RESC1005-STAR 5178.35,1480.32 r0 bottom locked (schematic designator R6)
R98 "270R 1%" RESC1005-STAR 5178.35,1381.89 r0 bottom locked (schematic designator R7)
R99 "270R 1%" RESC1005-STAR 5178.35,1283.47 r0 bottom locked (schematic designator R8)
R100 "270R 1%" RESC1005-STAR 9861.4,1411.28 r270 bottom (schematic designator R1)
R101 "270R 1%" RESC1005-STAR 9761.4,1411.28 r270 bottom (schematic designator R2)
R102 "270R 1%" RESC1005-STAR 9661.4,1411.28 r270 bottom (schematic designator R3)
R103 "270R 1%" RESC1005-STAR 9561.4,1411.28 r270 bottom (schematic designator R4)
R104 "270R 1%" RESC1005-STAR 9461.4,1411.28 r270 bottom (schematic designator R5)
R105 "270R 1%" RESC1005-STAR 9361.4,1411.28 r270 bottom (schematic designator R6)
R106 "270R 1%" RESC1005-STAR 9261.4,1411.28 r270 bottom (schematic designator R7)
R107 "270R 1%" RESC1005-STAR 9161.4,1411.28 r270 bottom (schematic designator R8)
R108 "3K3 1%" RESC1005-STAR 2755.91,5037.4 r270 bottom locked (schematic designator R6)
R109 "47K 1%" RESC1005-STAR 2874.02,5037.4 r90 bottom locked (schematic designator R7)
R110 "100K 1%" RESC1005-STAR 4531.49,5032.72 r180 bottom (schematic designator R19)
R111 "100K 1%" RESC1005-STAR 4531.49,5117.37 r180 bottom (schematic designator R10)
R112 "47K 1%" RESC1005-STAR 2992.13,5037.4 r90 bottom locked (schematic designator R8)
R113 "47K 1%" RESC1005-STAR 3346.46,5037.4 r90 bottom locked (schematic designator R9)
R114 "47K 1%" RESC1005-STAR 3582.68,5037.4 r90 bottom locked (schematic designator R12)
R115 "47K 1%" RESC1005-STAR 2759.84,5198.82 r270 bottom locked (schematic designator R28)
R116 "68K 1%" RESC1005-STAR 3346.46,5198.82 r90 bottom locked (schematic designator R11)
R117 "22K 1%" RESC1005-STAR 3228.68,5393.45 r90 bottom (schematic designator R50)
R118 "100K 1%" RESC1005-STAR 3021.08,5393.45 r270 bottom (schematic designator R51)
R119 "100K 1%" RESC1005-STAR 3228.35,5198.82 r270 bottom locked (schematic designator R15)
R120 "68K 1%" RESC1005-STAR 3464.57,5198.82 r90 bottom locked (schematic designator R18)
R121 "47K 1%" RESC1005-STAR 2874.02,5198.82 r270 bottom locked (schematic designator R29)
R122 "1K 1%" RESC1005-STAR 4866.13,4784.14 r270 bottom (schematic designator R16)
R123 "1K 1%" RESC1005-STAR 4866.13,5299.2 r90 bottom (schematic designator R13)
R124 "47K 1%" RESC1005-STAR 3110.24,5037.4 r90 bottom locked (schematic designator R17)
R125 "47K 1%" RESC1005-STAR 3228.35,5037.4 r90 bottom locked (schematic designator R20)
R126 "47K 1%" RESC1005-STAR 3700.79,5198.82 r270 bottom locked (schematic designator R22)
R127 "1K 1%" RESC1005-STAR 3110.24,5198.82 r270 bottom locked (schematic designator R21)
R128 "3K3 1%" RESC1005-STAR 3799.21,5037.4 r90 bottom locked (schematic designator R23)
R129 "47K 1%" RESC1005-STAR 3582.68,5198.82 r270 bottom locked (schematic designator R24)
R130 "1K 1%" RESC1005-STAR 3346.46,5588.58 r270 bottom locked (schematic designator R26)
R131 "2K2 1%" RESC1005-STAR 3464.57,5588.58 r270 bottom locked (schematic designator R25)
R132 "2K2 1%" RESC1005-STAR 2992.13,5198.82 r90 bottom locked (schematic designator R27)
R133 "47K 1%" RESC1005-STAR 4014.17,5751.58 r90 bottom locked (schematic designator R5)
R134 "47K 1%" RESC1005-STAR 3464.57,5037.4 r270 bottom locked (schematic designator R4)
R135 "220R 1%" RESC1005-STAR 2917.32,5751.97 r180 bottom (schematic designator R2MIC)
R136 "2K2 1%" RESC1005-STAR 2917.32,5889.76 r180 bottom (schematic designator R1MIC)
R137 "10K 1%" RESC1005-STAR 5267.71,5035.42 r180 bottom (schematic designator R1)
R138 "120R 1%" RESC1005-STAR 5653.13,4398.03 r270 bottom (schematic designator R5)
R139 "120R 1%" RESC1005-STAR 5401.17,4398.03 r90 bottom (schematic designator R2)
R140 "120R 1%" RESC1005-STAR 5570.46,4398.03 r270 bottom (schematic designator R4)
R141 "120R 1%" RESC1005-STAR 5483.84,4398.03 r90 bottom (schematic designator R6)
R142 "2K2 1%" RESC1005-STAR 928.68,2958.45 r180 bottom (schematic designator R1)
R143 "2K2 1%" RESC1005-STAR 3328.68,3113.45 r180 bottom (schematic designator R1)
R144 "2K2 1%" RESC1005-STAR 4511.81,3243.48 r270 bottom (schematic designator R1)
R145 "4K7 1%" RESC1005-STAR 10486.28,1639.3 r90 bottom (schematic designator R8)
R146 "4K7 1%" RESC1005-STAR 10530.57,1639.3 r90 bottom (schematic designator R7)
R147 "4K7 1%" RESC1005-STAR 10574.86,1639.3 r90 bottom (schematic designator R6)
R148 "4K7 1%" RESC1005-STAR 10619.15,1639.3 r90 bottom (schematic designator R5)
R149 "4K7 1%" RESC1005-STAR 10663.44,1639.3 r90 bottom (schematic designator R4)
R150 "4K7 1%" RESC1005-STAR 10707.73,1639.3 r90 bottom (schematic designator R3)
R151 "4K7 1%" RESC1005-STAR 10752.03,1639.3 r90 bottom (schematic designator R2)
R152 "4K7 1%" RESC1005-STAR 10796.32,1639.3 r90 bottom (schematic designator R1)
R153 "4K7 1%" RESC1005-STAR 10353.41,1639.3 r270 bottom (schematic designator R1)
R154 "4K7 1%" RESC1005-STAR 10397.7,1639.3 r270 bottom (schematic designator R2)
R155 "4K7 1%" RESC1005-STAR 10441.99,1639.3 r90 bottom (schematic designator R3)
R156 "4K7 1%" RESC1005-STAR 10840.61,1639.3 r270 bottom (schematic designator R4)
R157 "4K7 1%" RESC1005-STAR 10884.9,1639.3 r90 bottom (schematic designator R5)
R158 "4K7 1%" RESC1005-STAR 6016.82,1915 r0 bottom locked (schematic designator R1)
R159 "4K7 1%" RESC1005-STAR 8983.28,3843.38 r0 bottom (schematic designator R1)
R160 "10K 1%" RESC1005-STAR 6580.8,4517.47 r0 bottom (schematic designator R1)
R161 "1K 1%" RESC1005-STAR 6580.8,4567.47 r0 bottom (schematic designator R2)
R162 "0R047 1%" RESC3216 2431.1,3661.42 r270 bottom (schematic designator R27_CS)
R163 "0R047 1%" RESC3216 2647.64,3868.11 r270 bottom (schematic designator R32_CS)
R164 "0R047 1%" RESC3216 925.2,3149.61 r270 bottom (schematic designator R20_CS)
R165 "0R047 1%" RESC3216 2332.68,3661.42 r270 bottom (schematic designator R28_CS)
R166 "0R047 1%" RESC3216 2844.49,3868.11 r270 bottom (schematic designator R33_CS)
R167 "0R047 1%" RESC3216 826.77,3149.61 r270 bottom (schematic designator R21_CS)
R168 "0R047 1%" RESC3216 2234.25,3661.42 r270 bottom (schematic designator R29_CS)
R169 "0R047 1%" RESC3216 2746.06,3868.11 r270 bottom (schematic designator R34_CS)
R170 "0R047 1%" RESC3216 728.35,3149.61 r270 bottom (schematic designator R22_CS)
R171 "0R047 1%" RESC3216 2037.4,3661.42 r270 bottom (schematic designator R30_CS)
R172 "0R047 1%" RESC3216 2942.91,3868.11 r270 bottom (schematic designator R35_CS)
R173 "0R047 1%" RESC3216 629.92,3149.61 r270 bottom (schematic designator R23_CS)
R174 "0R047 1%" RESC3216 2135.83,3661.42 r270 bottom (schematic designator R31_CS)
R175 "0R047 1%" RESC3216 2549.21,3868.11 r270 bottom (schematic designator R36_CS)
R176 "0R047 1%" RESC3216 531.5,3149.61 r270 bottom (schematic designator R24_CS)
R177 "0R047 1%" RESC3216 7883.86,3710.63 r270 bottom (schematic designator R25_CS)
R178 "0R047 1%" RESC3216 5602.45,1117.51 r270 bottom (schematic designator R37_CS)
R179 "0R047 1%" RESC3216 8011.81,3710.63 r270 bottom (schematic designator R26_CS)
R180 "0R047 1%" RESC3216 6673.79,1092.98 r270 bottom (schematic designator R38_CS)
R181 "10K 1%" RESC1005-STAR 4998.03,4368.11 r90 bottom (schematic designator R5_CS)
R182 "10K 1%" RESC1005-STAR 4745.8,4368.11 r90 bottom (schematic designator R7_CS)
R183 "10K 1%" RESC1005-STAR 4489.11,4493.8 r270 bottom (schematic designator R9_CS)
R184 "2K7 1%" RESC1005-STAR 4528.77,4207.31 r270 bottom (schematic designator R14_CS)
R185 "2K7 1%" RESC1005-STAR 4578.74,4207.31 r270 bottom (schematic designator R13_CS)
R186 "10K 1%" RESC1005-STAR 4955.22,4368.11 r90 bottom (schematic designator R6_CS)
R187 "2K7 1%" RESC1005-STAR 4789.8,4368.11 r90 bottom (schematic designator R8_CS)
R188 "10K 1%" RESC1005-STAR 4456.69,4562.99 r180 bottom (schematic designator R10_CS)
R189 "120R 1%" RESC1005-STAR 5314.55,4398.03 r270 bottom (schematic designator R7)
R190 "4K7 1%" RESC1005-STAR 2086.61,3474.41 r90 bottom locked (schematic designator R1)
R191 "4K7 1%" RESC1005-STAR 2165.35,3474.41 r90 bottom locked (schematic designator R2)
R192 "4K7 1%" RESC1005-STAR 1929.13,3474.41 r90 bottom locked (schematic designator R3)
R193 "4K7 1%" RESC1005-STAR 2007.87,3474.41 r90 bottom locked (schematic designator R4)
R194 "100R 1%" RESC1005-STAR 2086.61,3301.18 r270 bottom locked (schematic designator R5)
R195 "100R 1%" RESC1005-STAR 2165.35,3301.18 r270 bottom locked (schematic designator R6)
R196 "100R 1%" RESC1005-STAR 1929.13,3301.18 r270 bottom locked (schematic designator R7)
R197 "100R 1%" RESC1005-STAR 2007.87,3301.18 r270 bottom locked (schematic designator R8)
R198 "4K7 1%" RESC1005-STAR 1850.39,3476.38 r90 bottom locked (schematic designator R9)
R199 "4K7 1%" RESC1005-STAR 1771.65,3476.38 r90 bottom locked (schematic designator R10)
R200 "4K7 1%" RESC1005-STAR 1614.17,3476.38 r90 bottom locked (schematic designator R11)
R201 "4K7 1%" RESC1005-STAR 1692.91,3476.38 r90 bottom locked (schematic designator R12)
R202 "100R 1%" RESC1005-STAR 1850.39,3299.21 r270 bottom locked (schematic designator R13)
R203 "100R 1%" RESC1005-STAR 1771.65,3299.21 r270 bottom locked (schematic designator R14)
R204 "100R 1%" RESC1005-STAR 1614.17,3301.18 r270 bottom locked (schematic designator R15)
R205 "100R 1%" RESC1005-STAR 1692.91,3301.18 r270 bottom locked (schematic designator R16)
R206 "4K7 1%" RESC1005-STAR 1535.43,3476.38 r90 bottom locked (schematic designator R17)
R207 "100R 1%" RESC1005-STAR 1535.43,3301.18 r270 bottom locked (schematic designator R18)
R208 "4K7 1%" RESC1005-STAR 4950.79,3165.35 r0 bottom locked (schematic designator R1)
R209 "4K7 1%" RESC1005-STAR 4950.79,3086.61 r0 bottom locked (schematic designator R2)
R210 "4K7 1%" RESC1005-STAR 4950.79,3322.84 r0 bottom locked (schematic designator R3)
R211 "4K7 1%" RESC1005-STAR 4950.79,3244.1 r0 bottom locked (schematic designator R4)
R212 "100R 1%" RESC1005-STAR 4763.78,3165.35 r180 bottom locked (schematic designator R5)
R213 "100R 1%" RESC1005-STAR 4763.78,3086.61 r180 bottom locked (schematic designator R6)
R214 "100R 1%" RESC1005-STAR 4763.78,3322.84 r180 bottom locked (schematic designator R7)
R215 "100R 1%" RESC1005-STAR 4763.78,3244.1 r180 bottom locked (schematic designator R8)
R216 "4K7 1%" RESC1005-STAR 4950.79,3401.58 r0 bottom locked (schematic designator R9)
R217 "4K7 1%" RESC1005-STAR 4950.79,3480.32 r0 bottom locked (schematic designator R10)
R218 "4K7 1%" RESC1005-STAR 4950.79,3637.8 r0 bottom locked (schematic designator R11)
R219 "4K7 1%" RESC1005-STAR 4950.79,3559.06 r0 bottom locked (schematic designator R12)
R220 "100R 1%" RESC1005-STAR 4761.81,3401.58 r180 bottom locked (schematic designator R13)
R221 "100R 1%" RESC1005-STAR 4761.81,3480.32 r180 bottom locked (schematic designator R14)
R222 "100R 1%" RESC1005-STAR 4761.81,3637.8 r180 bottom locked (schematic designator R15)
R223 "100R 1%" RESC1005-STAR 4761.81,3559.06 r180 bottom locked (schematic designator R16)
R224 "4K7 1%" RESC1005-STAR 4950.79,3716.54 r0 bottom locked (schematic designator R17)
R225 "100R 1%" RESC1005-STAR 4761.81,3716.54 r180 bottom locked (schematic designator R18)
R226 "4K7 1%" RESC1005-STAR 2572.05,3571.11 r180 bottom (schematic designator R1)
R227 "4K7 1%" RESC1005-STAR 2572.05,3488.19 r180 bottom locked (schematic designator R2)
R228 "4K7 1%" RESC1005-STAR 2397.24,3173.23 r180 bottom locked (schematic designator R3)
R229 "4K7 1%" RESC1005-STAR 2397.24,3251.97 r180 bottom locked (schematic designator R4)
R230 "100R 1%" RESC1005-STAR 2572.05,3330.71 r0 bottom locked (schematic designator R5)
R231 "100R 1%" RESC1005-STAR 2572.05,3409.45 r0 bottom locked (schematic designator R6)
R232 "100R 1%" RESC1005-STAR 2572.05,3173.23 r0 bottom locked (schematic designator R7)
R233 "100R 1%" RESC1005-STAR 2572.05,3251.97 r0 bottom locked (schematic designator R8)
R234 "4K7 1%" RESC1005-STAR 2397.24,3094.49 r180 bottom locked (schematic designator R9)
R235 "4K7 1%" RESC1005-STAR 2397.24,3015.75 r180 bottom locked (schematic designator R10)
R236 "4K7 1%" RESC1005-STAR 2397.24,2858.27 r180 bottom locked (schematic designator R11)
R237 "4K7 1%" RESC1005-STAR 2397.24,2937.01 r180 bottom locked (schematic designator R12)
R238 "100R 1%" RESC1005-STAR 2572.05,3094.49 r0 bottom locked (schematic designator R13)
R239 "100R 1%" RESC1005-STAR 2572.05,3015.75 r0 bottom locked (schematic designator R14)
R240 "100R 1%" RESC1005-STAR 2570.08,2858.27 r0 bottom locked (schematic designator R15)
R241 "100R 1%" RESC1005-STAR 2570.08,2937.01 r0 bottom locked (schematic designator R16)
R242 "4K7 1%" RESC1005-STAR 2397.24,2779.53 r180 bottom locked (schematic designator R17)
R243 "100R 1%" RESC1005-STAR 2570.08,2779.53 r0 bottom locked (schematic designator R18)
R244 "4K7 1%" RESC1005-STAR 3007.87,785.43 r90 bottom locked (schematic designator R1)
R245 "4K7 1%" RESC1005-STAR 2929.13,785.43 r90 bottom locked (schematic designator R2)
R246 "4K7 1%" RESC1005-STAR 3165.35,785.43 r90 bottom locked (schematic designator R3)
R247 "4K7 1%" RESC1005-STAR 3086.61,785.43 r90 bottom locked (schematic designator R4)
R248 "100R 1%" RESC1005-STAR 3007.87,645.67 r270 bottom (schematic designator R5)
R249 "100R 1%" RESC1005-STAR 2929.13,645.67 r270 bottom (schematic designator R6)
R250 "100R 1%" RESC1005-STAR 3165.35,645.67 r270 bottom (schematic designator R7)
R251 "100R 1%" RESC1005-STAR 3086.61,645.67 r270 bottom (schematic designator R8)
R252 "4K7 1%" RESC1005-STAR 3244.09,785.43 r90 bottom locked (schematic designator R9)
R253 "4K7 1%" RESC1005-STAR 3322.83,785.43 r90 bottom locked (schematic designator R10)
R254 "4K7 1%" RESC1005-STAR 3480.32,785.43 r90 bottom locked (schematic designator R11)
R255 "4K7 1%" RESC1005-STAR 3401.57,785.43 r90 bottom locked (schematic designator R12)
R256 "100R 1%" RESC1005-STAR 3244.09,645.67 r270 bottom (schematic designator R13)
R257 "100R 1%" RESC1005-STAR 3322.83,645.67 r270 bottom (schematic designator R14)
R258 "100R 1%" RESC1005-STAR 3480.32,645.67 r270 bottom (schematic designator R15)
R259 "100R 1%" RESC1005-STAR 3401.57,645.67 r270 bottom (schematic designator R16)
R260 "4K7 1%" RESC1005-STAR 3559.06,785.43 r90 bottom locked (schematic designator R17)
R261 "100R 1%" RESC1005-STAR 3559.06,645.67 r270 bottom (schematic designator R18)
R262 "4K7 1%" RESC1005-STAR 3913.39,785.43 r90 bottom locked (schematic designator R1)
R263 "4K7 1%" RESC1005-STAR 3834.65,785.43 r90 bottom locked (schematic designator R2)
R264 "4K7 1%" RESC1005-STAR 4070.87,785.43 r90 bottom locked (schematic designator R3)
R265 "4K7 1%" RESC1005-STAR 3992.13,785.43 r90 bottom locked (schematic designator R4)
R266 "100R 1%" RESC1005-STAR 3913.39,643.7 r270 bottom (schematic designator R5)
R267 "100R 1%" RESC1005-STAR 3834.65,643.7 r270 bottom (schematic designator R6)
R268 "100R 1%" RESC1005-STAR 4070.87,643.7 r270 bottom (schematic designator R7)
R269 "100R 1%" RESC1005-STAR 3992.13,643.7 r270 bottom (schematic designator R8)
R270 "4K7 1%" RESC1005-STAR 4149.61,785.43 r90 bottom locked (schematic designator R9)
R271 "4K7 1%" RESC1005-STAR 4228.35,785.43 r90 bottom locked (schematic designator R10)
R272 "4K7 1%" RESC1005-STAR 4385.83,785.43 r90 bottom locked (schematic designator R11)
R273 "4K7 1%" RESC1005-STAR 4307.09,785.43 r90 bottom locked (schematic designator R12)
R274 "100R 1%" RESC1005-STAR 4149.61,643.7 r270 bottom (schematic designator R13)
R275 "100R 1%" RESC1005-STAR 4228.35,643.7 r270 bottom (schematic designator R14)
R276 "100R 1%" RESC1005-STAR 4385.83,643.7 r270 bottom (schematic designator R15)
R277 "100R 1%" RESC1005-STAR 4307.09,643.7 r270 bottom (schematic designator R16)
R278 "4K7 1%" RESC1005-STAR 4464.57,785.43 r90 bottom locked (schematic designator R17)
R279 "100R 1%" RESC1005-STAR 4464.57,643.7 r270 bottom (schematic designator R18)
R280 "4K7 1%" RESC1005-STAR 844.49,4417.32 r0 bottom locked (schematic designator R3_HJ)
R281 "4K7 1%" RESC1005-STAR 844.49,4515.75 r0 bottom locked (schematic designator R2_HJ)
R282 "4K7 1%" RESC1005-STAR 844.49,4318.9 r0 bottom locked (schematic designator R1_HJ)
R283 "4K7 1%" RESC1005-STAR 844.49,4220.47 r0 bottom locked (schematic designator R4_HJ)
R284 "100R 1%" RESC1005-STAR 667.32,4417.32 r180 bottom locked (schematic designator R7_HJ)
R285 "100R 1%" RESC1005-STAR 667.32,4515.75 r180 bottom locked (schematic designator R6_HJ)
R286 "100R 1%" RESC1005-STAR 667.32,4318.9 r180 bottom locked (schematic designator R5_HJ)
R287 "100R 1%" RESC1005-STAR 667.32,4220.47 r180 bottom locked (schematic designator R8_HJ)
R288 "4K7 1%" RESC1005-STAR 844.49,4122.05 r0 bottom locked (schematic designator R9_HJ)
R289 "4K7 1%" RESC1005-STAR 844.49,4023.62 r0 bottom locked (schematic designator R12_HJ)
R290 "4K7 1%" RESC1005-STAR 844.49,3826.77 r0 bottom locked (schematic designator R11_HJ)
R291 "4K7 1%" RESC1005-STAR 844.49,3925.2 r0 bottom locked (schematic designator R10_HJ)
R292 "100R 1%" RESC1005-STAR 667.32,4122.05 r180 bottom locked (schematic designator R13_HJ)
R293 "100R 1%" RESC1005-STAR 667.32,4023.62 r180 bottom locked (schematic designator R16_HJ)
R294 "100R 1%" RESC1005-STAR 667.32,3826.77 r180 bottom locked (schematic designator R15_HJ)
R295 "100R 1%" RESC1005-STAR 667.32,3925.2 r180 bottom locked (schematic designator R14_HJ)
R296 "1K 1%" RESC1005-STAR 661.42,5337.01 r180 bottom locked (schematic designator R6)
R297 "4K7 1%" RESC1005-STAR 661.42,5277.95 r0 bottom locked (schematic designator R2)
R298 "4K7 1%" RESC1005-STAR 661.42,5218.9 r0 bottom locked (schematic designator R1)
R299 "4K7 1%" RESC1005-STAR 661.42,5100.79 r0 bottom locked (schematic designator R4)
R300 "4K7 1%" RESC1005-STAR 661.42,5041.73 r0 bottom locked (schematic designator R3)
R301 "100R 1%" RESC1005-STAR 661.42,5159.84 r0 bottom locked (schematic designator R5)
R302 "1K 1%" RESC1005-STAR 661.42,5396.06 r0 bottom locked (schematic designator R7)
